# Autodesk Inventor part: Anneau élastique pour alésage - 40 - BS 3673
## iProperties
Shininess: 64.0
Length Units: 11269
Angle Units: 11279
Time Units: 11290
Mass Units: 11283
Length Display Precision: 3
Angle Display Precision: 2
Compacted: True
Part Number: Anneau élastique pour alésage - 40 - BS 3673
Document SubType Name: Modeling
Created: 2005-02
Material: Par défaut
Designer: LEGERET Philippe
Catalog Web Link: www.traceparts.com
Description: Anneau élastique pour alésage Ø40 - BS 3673
Density: 0.0
Volumn: 0.0
Area: 0.0
PropertySet Name: Model Information
Control State: 0
Master: False
Checked Out: False
Author: Trace Parts S.A.
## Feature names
1. Base1
